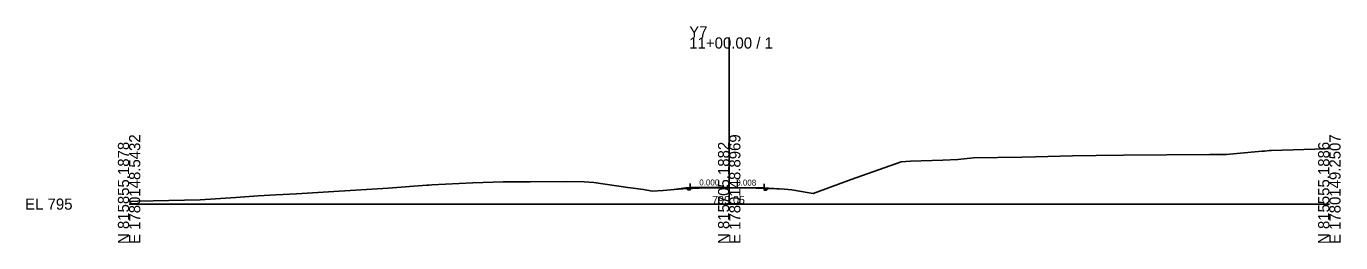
# Model space of a CAD drawing. Extents: x -26 to 2903, y -10 to 5536.
# Drawn here: x -25.7 to 302.8, y 990.3 to 1044.6 of the extents above; entities that cross this region are included whole.
import ezdxf

# ---------------------------------------------------------------- set-up
doc = ezdxf.new("R2010")
doc.units = 0
for name, color, linetype in [('Exist Cross Section Cell', 7, 'Continuous'), ('Exist XS Center Line Elevation Label', 7, 'Continuous'), ('Exist XS Ground Line', 7, 'Continuous'), ('Prop XS Dump Level', 7, 'Continuous'), ('Prop XS Earthwork Shape', 7, 'Continuous'), ('Prop XS EOT Tick Mark', 7, 'Continuous'), ('Prop XS Finish Grade', 7, 'Continuous'), ('Prop XS Finish Grade Earthwork', 7, 'Continuous'), ('Prop XS Finish Grade Pavement', 7, 'Continuous'), ('Prop XS Pvmt Edge Slope', 7, 'Continuous'), ('Prop XS SE Text', 7, 'Continuous'), ('Prop XS Subgrade Earthwork', 7, 'Continuous')]:
    doc.layers.add(name, color=color, linetype=linetype)

msp = doc.modelspace()

# ---------------------------------------------------------------- linework, layer by layer
at = {"layer": 'Exist Cross Section Cell'}
for p, q in [((150, 1000), (150, 1041.78)), ((0, 1000), (150, 1000)), ((150, 1000), (300, 1000))]:
    msp.add_line(p, q, dxfattribs=at)
at = {"layer": 'Exist XS Ground Line'}
for p, q in [((226.56, 1011.87), (235.81, 1012.1)), ((235.81, 1012.1), (241.73, 1012.14)), ((241.73, 1012.14), (248.55, 1012.26)), ((248.55, 1012.26), (270.12, 1012.4)), ((270.12, 1012.4), (274.28, 1012.46)), ((274.28, 1012.46), (276.87, 1012.7)), ((276.87, 1012.7), (283.18, 1013.25)), ((283.18, 1013.25), (283.77, 1013.3)), ((283.77, 1013.3), (285.02, 1013.43)), ((285.02, 1013.43), (285.58, 1013.45)), ((285.58, 1013.45), (299.07, 1013.89)), ((299.07, 1013.89), (300, 1013.93)), ((180.5, 1006.18), (192.99, 1010.62)), ((192.99, 1010.62), (195.27, 1010.72)), ((195.27, 1010.72), (203.43, 1011.05)), ((203.43, 1011.05), (207.15, 1011.22)), ((207.15, 1011.22), (211.02, 1011.6)), ((211.02, 1011.6), (223.17, 1011.79)), ((223.17, 1011.79), (226.56, 1011.87)), ((75.65, 1004.82), (85.94, 1005.35)), ((85.94, 1005.35), (93.48, 1005.56)), ((93.48, 1005.56), (100.28, 1005.62)), ((100.28, 1005.62), (109.37, 1005.67)), ((109.37, 1005.67), (113.71, 1005.62)), ((113.71, 1005.62), (116.18, 1005.42)), ((116.18, 1005.42), (124.69, 1004.19)), ((170.96, 1002.66), (180.5, 1006.18)), ((26.67, 1001.68), (32.29, 1002.05)), ((32.29, 1002.05), (36.66, 1002.31)), ((36.66, 1002.31), (41.88, 1002.61)), ((41.88, 1002.61), (51.19, 1003.13)), ((51.19, 1003.13), (64.72, 1003.97)), ((64.72, 1003.97), (74.43, 1004.75)), ((74.43, 1004.75), (74.94, 1004.78)), ((74.94, 1004.78), (75.65, 1004.82)), ((124.69, 1004.19), (128.58, 1003.64)), ((128.58, 1003.64), (130.76, 1003.26)), ((130.76, 1003.26), (133.45, 1003.39)), ((133.45, 1003.39), (136.27, 1003.63)), ((136.27, 1003.63), (139.46, 1003.94)), ((139.46, 1003.94), (140.25, 1003.96)), ((140.25, 1003.96), (142.47, 1003.97)), ((142.47, 1003.97), (150.02, 1004.05)), ((150.02, 1004.05), (156.62, 1003.98)), ((156.62, 1003.98), (158.71, 1003.95)), ((158.71, 1003.95), (159.89, 1003.91)), ((159.89, 1003.91), (163.85, 1003.73)), ((163.85, 1003.73), (165.66, 1003.56)), ((165.66, 1003.56), (169.95, 1002.84)), ((169.95, 1002.84), (170.96, 1002.66)), ((0, 1000.64), (2.14, 1000.7)), ((2.14, 1000.7), (17.75, 1001.11)), ((17.75, 1001.11), (26.67, 1001.68))]:
    msp.add_line(p, q, dxfattribs=at)
at = {"layer": 'Prop XS Dump Level'}
for p, q in [((150, 1004.17), (140.25, 1004.17)), ((158.71, 1004.11), (150, 1004.17))]:
    msp.add_line(p, q, dxfattribs=at)
at = {"layer": 'Prop XS Earthwork Shape'}
for points in [[(139.33, 1003.92), (139.15, 1004.11), (136.27, 1003.63)], [(139.33, 1003.92), (139.46, 1003.94), (140.25, 1003.96), (140.25, 1003.59), (139.66, 1003.59)], [(158.71, 1003.95), (159.7, 1003.92), (159.3, 1003.52), (158.71, 1003.52)], [(159.7, 1003.92), (159.89, 1003.91), (163.85, 1003.73), (159.81, 1004.03)]]:
    msp.add_lwpolyline(points, close=True, dxfattribs=at)
at = {"layer": 'Prop XS EOT Tick Mark'}
for p, q in [((140.25, 1004.17), (140.25, 1005.17)), ((140.25, 1004.17), (140.25, 1005.17)), ((158.71, 1004.11), (158.71, 1005.11)), ((158.71, 1004.11), (158.71, 1005.11))]:
    msp.add_line(p, q, dxfattribs=at)
at = {"layer": 'Prop XS Finish Grade'}
for p, q in [((140.25, 1004.17), (139.15, 1004.11)), ((158.71, 1004.11), (159.81, 1004.03))]:
    msp.add_line(p, q, dxfattribs=at)
at = {"layer": 'Prop XS Finish Grade Earthwork'}
for p, q in [((139.15, 1004.11), (136.27, 1003.63)), ((159.81, 1004.03), (163.85, 1003.73))]:
    msp.add_line(p, q, dxfattribs=at)
at = {"layer": 'Prop XS Finish Grade Pavement'}
for p, q in [((140.25, 1004.17), (150, 1004.17)), ((150, 1004.17), (158.71, 1004.11))]:
    msp.add_line(p, q, dxfattribs=at)
at = {"layer": 'Prop XS Pvmt Edge Slope'}
for p, q in [((140.25, 1004.17), (139.66, 1003.59)), ((140.25, 1004.17), (139.7, 1003.63)), ((158.71, 1004.11), (159.3, 1003.52)), ((158.71, 1004.11), (159.26, 1003.56))]:
    msp.add_line(p, q, dxfattribs=at)
at = {"layer": 'Prop XS Subgrade Earthwork'}
for p, q in [((139.66, 1003.59), (139.15, 1004.11)), ((140.25, 1003.59), (139.66, 1003.59)), ((140.25, 1003.59), (140.25, 1003.96)), ((158.71, 1003.52), (158.71, 1003.95)), ((159.3, 1003.52), (158.71, 1003.52)), ((159.3, 1003.52), (159.81, 1004.03))]:
    msp.add_line(p, q, dxfattribs=at)

# ---------------------------------------------------------------- texts
at = {"layer": 'Exist Cross Section Cell'}
for s, p in [('Y7', (140, 1041.78)), ('11+00.00 / 1', (140, 1038.98)), ('EL 795', (-26, 998.6))]:
    msp.add_text(s, height=2.8, dxfattribs=at).set_placement(p)
for s, p in [('N 815855.1878', (0, 990)), ('E 1780148.5432', (2.8, 990)), ('N 815705.1882', (150, 990)), ('E 1780148.8969', (152.8, 990)), ('N 815555.1886', (300, 990)), ('E 1780149.2507', (302.8, 990))]:
    msp.add_text(s, height=2.8, rotation=90, dxfattribs=at).set_placement(p)
at = {"layer": 'Exist XS Center Line Elevation Label'}
msp.add_text('799.05', height=2, dxfattribs=at).set_placement((145.74, 1000.05))
at = {"layer": 'Prop XS Dump Level'}
for s, height, p in [('Case1', 0.04, (136.25, 1003.89)), ('Eop', 0.3, (140.25, 1003.66)), ('Eop', 0.3, (140.25, 1003.66)), ('Eop', 0.3, (158.71, 1003.65)), ('Eop', 0.3, (158.71, 1003.65))]:
    msp.add_text(s, height=height, dxfattribs=at).set_placement(p)
at = {"layer": 'Prop XS SE Text'}
for s, rotation, p in [('0.000', 359.9989, (142.5, 1004.67)), ('0.000', 359.9989, (142.5, 1004.67)), ('0.008', 359.5474, (151.74, 1004.66)), ('0.008', 359.5474, (151.74, 1004.66))]:
    msp.add_text(s, height=1.5, rotation=rotation, dxfattribs=at).set_placement(p)

doc.saveas('drawing.dxf')
